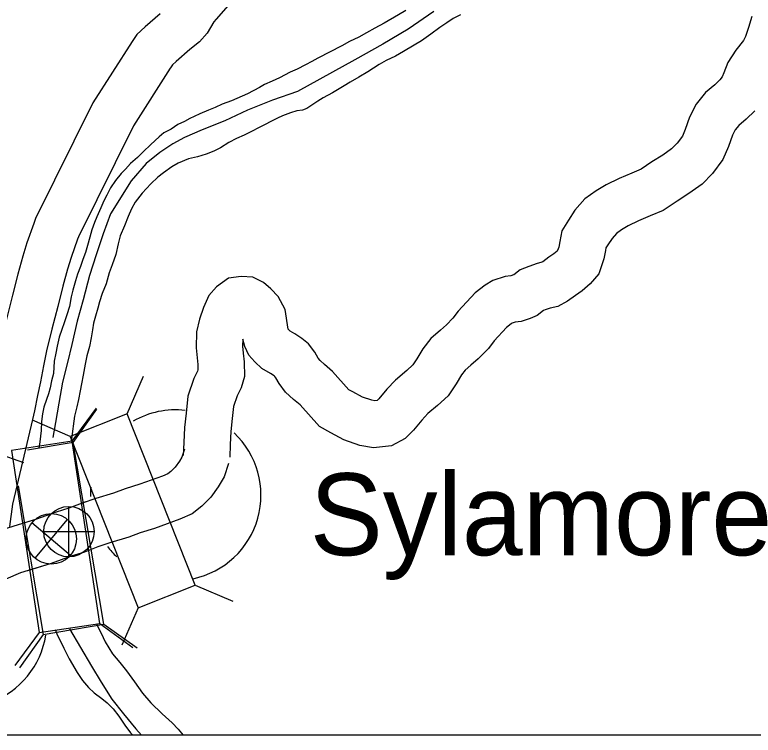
# Model space of a CAD drawing. Extents: x 1377389 to 1380723, y 1168351 to 1170484.
# Drawn here: x 1377861.18 to 1377908.8, y 1169604.28 to 1169650.73 of the extents above; entities that cross this region are included whole.
import ezdxf

# ---------------------------------------------------------------- set-up
doc = ezdxf.new("R2010")
doc.units = 0
doc.layers.add('B_Fill', color=7, linetype='Continuous')
doc.layers.add('B_Text', color=7, linetype='Continuous')

msp = doc.modelspace()

# ---------------------------------------------------------------- linework, layer by layer
at = {"layer": 'B_Fill'}
for p, q in [((1377868.434, 1169625.009), (1377869.481, 1169627.432)), ((1377864.89, 1169623.242), (1377866.456, 1169625.368)), ((1377864.942, 1169623.153), (1377866.471, 1169625.305)), ((1377864.753, 1169623.549), (1377862.329, 1169624.596)), ((1377861.775, 1169621.842), (1377854.923, 1169624.283)), ((1377864.942, 1169623.153), (1377861.997, 1169622.654)), ((1377866.927, 1169611.44), (1377864.942, 1169623.153)), ((1377861.398, 1169620.367), (1377863.023, 1169610.778)), ((1377864.674, 1169615.783), (1377864.674, 1169619.033)), ((1377862.294, 1169617.988), (1377864.783, 1169615.899)), ((1377862.494, 1169615.699), (1377864.583, 1169618.188)), ((1377863.049, 1169617.408), (1377866.299, 1169617.408)), ((1377872.813, 1169613.966), (1377875.236, 1169612.918)), ((1377869.132, 1169612.506), (1377868.085, 1169610.082)), ((1377863.023, 1169610.778), (1377866.927, 1169611.44)), ((1377866.67, 1169611.496), (1377868.795, 1169609.93)), ((1377866.927, 1169611.44), (1377869.079, 1169609.911)), ((1377862.754, 1169610.903), (1377861.188, 1169608.778)), ((1377863.023, 1169610.778), (1377861.494, 1169608.626))]:
    msp.add_line(p, q, dxfattribs=at)
for points in [[(1377874.94, 1169651.321), (1377874.171, 1169650.441), (1377874.024, 1169650.265), (1377873.8, 1169649.909), (1377873.579, 1169649.536), (1377873.097, 1169648.977), (1377872.473, 1169648.484), (1377871.587, 1169647.715), (1377871.346, 1169647.492), (1377871.221, 1169647.303), (1377871.206, 1169647.277)], [(1377886.404, 1169651.005), (1377885.931, 1169650.722), (1377884.995, 1169650.185), (1377884.402, 1169649.868), (1377883.86, 1169649.562), (1377883.377, 1169649.278), (1377882.773, 1169649.001), (1377882.27, 1169648.727), (1377880.72, 1169647.922), (1377880.335, 1169647.721), (1377879.93, 1169647.5), (1377879.397, 1169647.224), (1377878.931, 1169647.031), (1377878.25, 1169646.672), (1377877.775, 1169646.448), (1377877.291, 1169646.234), (1377876.955, 1169646.045), (1377876.195, 1169645.633), (1377875.166, 1169645.174), (1377874.561, 1169644.967), (1377874.096, 1169644.753), (1377873.671, 1169644.571), (1377873.116, 1169644.346), (1377872.75, 1169644.175), (1377872.463, 1169644.047), (1377872.118, 1169643.857), (1377871.693, 1169643.645), (1377871.26, 1169643.353), (1377870.786, 1169643.109), (1377870.492, 1169642.86), (1377870.228, 1169642.622), (1377869.945, 1169642.344), (1377869.486, 1169641.91), (1377869.086, 1169641.538), (1377868.646, 1169641.135), (1377868.325, 1169640.775), (1377868.042, 1169640.487), (1377867.674, 1169640.045), (1377867.366, 1169639.565), (1377867.118, 1169639.097), (1377866.917, 1169638.731), (1377866.729, 1169638.274), (1377866.464, 1169637.705), (1377866.323, 1169637.34), (1377866.156, 1169636.854), (1377866.028, 1169636.389), (1377865.881, 1169635.864), (1377865.753, 1169635.399), (1377865.575, 1169634.942), (1377865.417, 1169634.507), (1377865.229, 1169634.01), (1377865.091, 1169633.575), (1377864.926, 1169632.979), (1377864.828, 1169632.535), (1377864.704, 1169631.919), (1377864.548, 1169631.383), (1377864.371, 1169630.877), (1377864.212, 1169630.441), (1377864.045, 1169629.935), (1377863.91, 1169629.37), (1377863.822, 1169628.916), (1377863.715, 1169628.391), (1377863.686, 1169627.608), (1377863.558, 1169627.123), (1377863.46, 1169626.689), (1377863.35, 1169626.295), (1377863.229, 1169625.93), (1377863.062, 1169625.434), (1377862.973, 1169625.001), (1377862.916, 1169624.518), (1377862.891, 1169623.925), (1377862.8, 1169623.2), (1377862.743, 1169622.785)], [(1377886.404, 1169651.005), (1377885.931, 1169650.722), (1377884.995, 1169650.185), (1377884.402, 1169649.868), (1377883.86, 1169649.562), (1377883.377, 1169649.278), (1377882.773, 1169649.001), (1377882.27, 1169648.727), (1377880.72, 1169647.922), (1377880.335, 1169647.721), (1377879.93, 1169647.5), (1377879.397, 1169647.224), (1377878.931, 1169647.031), (1377878.25, 1169646.672), (1377877.775, 1169646.448), (1377877.291, 1169646.234), (1377876.955, 1169646.045), (1377876.195, 1169645.633), (1377875.166, 1169645.174), (1377874.561, 1169644.967), (1377874.096, 1169644.753), (1377873.671, 1169644.571), (1377873.116, 1169644.346), (1377872.75, 1169644.175), (1377872.463, 1169644.047), (1377872.118, 1169643.857), (1377871.693, 1169643.645), (1377871.26, 1169643.353), (1377870.786, 1169643.109), (1377870.492, 1169642.86), (1377870.228, 1169642.622), (1377869.945, 1169642.344), (1377869.486, 1169641.91), (1377869.086, 1169641.538), (1377868.646, 1169641.135), (1377868.325, 1169640.775), (1377868.042, 1169640.487), (1377867.674, 1169640.045), (1377867.366, 1169639.565), (1377867.118, 1169639.097), (1377866.917, 1169638.731), (1377866.729, 1169638.274), (1377866.464, 1169637.705), (1377866.323, 1169637.34), (1377866.156, 1169636.854), (1377866.028, 1169636.389), (1377865.881, 1169635.864), (1377865.753, 1169635.399), (1377865.575, 1169634.942), (1377865.417, 1169634.507), (1377865.229, 1169634.01), (1377865.091, 1169633.575), (1377864.926, 1169632.979), (1377864.828, 1169632.535), (1377864.704, 1169631.919), (1377864.548, 1169631.383), (1377864.371, 1169630.877), (1377864.212, 1169630.441), (1377864.045, 1169629.935), (1377863.91, 1169629.37), (1377863.822, 1169628.916), (1377863.715, 1169628.391), (1377863.686, 1169627.608), (1377863.558, 1169627.123), (1377863.46, 1169626.689), (1377863.35, 1169626.295), (1377863.229, 1169625.93), (1377863.062, 1169625.434), (1377862.973, 1169625.001), (1377862.916, 1169624.518), (1377862.891, 1169623.925), (1377862.8, 1169623.2), (1377862.779, 1169623.047)], [(1377888.208, 1169650.944), (1377886.556, 1169649.796), (1377884.91, 1169648.828), (1377883.115, 1169647.827), (1377879.405, 1169645.78), (1377877.798, 1169645.225), (1377876.193, 1169644.569), (1377874.73, 1169643.888), (1377873.263, 1169643.316), (1377872.135, 1169642.824), (1377871.375, 1169642.413), (1377870.539, 1169641.858), (1377869.657, 1169641.142), (1377868.695, 1169640.033), (1377867.349, 1169637.9), (1377866.873, 1169636.613), (1377866.438, 1169635.257), (1377866.002, 1169633.931), (1377865.603, 1169632.355), (1377865.209, 1169630.97), (1377864.858, 1169629.466), (1377864.578, 1169628.304), (1377864.271, 1169627.052), (1377864.027, 1169625.681), (1377863.799, 1169624.451), (1377863.631, 1169623.476)], [(1377889.925, 1169650.729), (1377889.451, 1169650.486), (1377889.048, 1169650.214), (1377888.595, 1169649.901), (1377888.006, 1169649.474), (1377887.406, 1169649.056), (1377886.934, 1169648.763), (1377886.244, 1169648.363), (1377885.731, 1169648.058), (1377885.138, 1169647.781), (1377884.684, 1169647.518), (1377883.946, 1169647.057), (1377883.364, 1169646.71), (1377882.802, 1169646.394), (1377882.428, 1169646.143), (1377881.679, 1169645.701), (1377881.067, 1169645.373), (1377880.722, 1169645.154), (1377880.398, 1169644.934), (1377880.014, 1169644.693), (1377879.726, 1169644.585), (1377879.377, 1169644.525), (1377878.96, 1169644.414), (1377878.445, 1169644.219), (1377878.128, 1169644.06), (1377876.894, 1169643.435), (1377876.479, 1169643.223), (1377875.975, 1169642.958), (1377875.48, 1169642.754), (1377874.977, 1169642.49), (1377874.455, 1169642.155), (1377874.02, 1169641.932), (1377873.515, 1169641.738), (1377872.969, 1169641.573), (1377872.391, 1169641.447), (1377871.728, 1169641.158), (1377871.314, 1169640.926), (1377870.774, 1169640.54), (1377870.411, 1169640.26), (1377869.951, 1169639.826), (1377869.407, 1169639.219), (1377868.941, 1169638.645), (1377868.702, 1169638.227), (1377868.485, 1169637.72)], [(1377889.925, 1169650.729), (1377889.451, 1169650.486), (1377889.048, 1169650.214), (1377888.595, 1169649.901), (1377888.006, 1169649.474), (1377887.406, 1169649.056), (1377886.934, 1169648.763), (1377886.244, 1169648.363), (1377885.731, 1169648.058), (1377885.138, 1169647.781), (1377884.684, 1169647.518), (1377883.946, 1169647.057), (1377883.364, 1169646.71), (1377882.802, 1169646.394), (1377882.428, 1169646.143), (1377881.679, 1169645.701), (1377881.067, 1169645.373), (1377880.722, 1169645.154), (1377880.398, 1169644.934), (1377880.014, 1169644.693), (1377879.726, 1169644.585), (1377879.377, 1169644.525), (1377878.96, 1169644.414), (1377878.445, 1169644.219), (1377878.128, 1169644.06), (1377876.894, 1169643.435), (1377876.479, 1169643.223), (1377875.975, 1169642.958), (1377875.48, 1169642.754), (1377874.977, 1169642.49), (1377874.455, 1169642.155), (1377874.02, 1169641.932), (1377873.515, 1169641.738), (1377872.969, 1169641.573), (1377872.391, 1169641.447), (1377871.728, 1169641.158), (1377871.314, 1169640.926), (1377870.774, 1169640.54), (1377870.411, 1169640.26), (1377869.951, 1169639.826), (1377869.407, 1169639.219), (1377868.941, 1169638.645), (1377868.702, 1169638.227), (1377868.485, 1169637.72)], [(1377870.559, 1169650.795), (1377869.585, 1169649.949), (1377869.044, 1169649.449), (1377868.756, 1169649.013)], [(1377908.71, 1169650.617), (1377908.487, 1169649.916), (1377908.306, 1169649.338), (1377908.158, 1169649.06), (1377907.671, 1169648.44), (1377907.165, 1169647.647), (1377906.91, 1169646.98), (1377906.79, 1169646.735), (1377906.636, 1169646.526), (1377906.318, 1169646.22), (1377905.727, 1169645.71), (1377905.11, 1169644.968), (1377904.695, 1169644.138), (1377904.412, 1169643.331), (1377904.228, 1169642.91), (1377903.89, 1169642.456), (1377903.535, 1169642.094), (1377902.967, 1169641.684), (1377902.265, 1169641.24), (1377901.562, 1169640.775), (1377900.968, 1169640.525), (1377900.155, 1169640.169), (1377899.311, 1169639.768), (1377898.662, 1169639.383), (1377897.947, 1169638.868), (1377897.303, 1169638.13), (1377896.882, 1169637.498), (1377896.466, 1169636.802), (1377896.321, 1169636.109), (1377896.258, 1169635.757), (1377896.181, 1169635.531), (1377896.148, 1169635.491), (1377895.944, 1169635.316), (1377895.615, 1169635.093), (1377895.222, 1169634.811), (1377895.111, 1169634.751), (1377894.862, 1169634.691), (1377894.333, 1169634.511), (1377893.773, 1169634.279), (1377893.365, 1169633.97), (1377893.347, 1169633.963), (1377893.169, 1169633.901), (1377892.797, 1169633.861), (1377892.006, 1169633.596), (1377891.505, 1169633.3), (1377890.864, 1169632.805), (1377889.762, 1169631.628), (1377889.425, 1169631.162), (1377889.01, 1169630.74), (1377888.624, 1169630.405), (1377888.002, 1169629.864), (1377887.496, 1169629.186), (1377887.109, 1169628.547), (1377886.848, 1169628.154), (1377886.457, 1169627.806), (1377885.726, 1169627.178), (1377885.175, 1169626.584), (1377884.663, 1169625.972), (1377884.552, 1169625.858), (1377884.402, 1169625.841), (1377884.195, 1169625.876), (1377883.612, 1169626.088), (1377882.978, 1169626.414), (1377882.723, 1169626.556), (1377881.677, 1169627.729), (1377881.151, 1169628.174), (1377880.871, 1169628.433), (1377880.744, 1169628.6), (1377880.529, 1169628.984), (1377880.121, 1169629.506), (1377879.688, 1169629.866), (1377879.248, 1169630.155), (1377878.937, 1169630.337), (1377878.828, 1169630.441), (1377878.821, 1169630.466), (1377878.613, 1169631.737), (1377878.165, 1169632.559), (1377877.695, 1169633.054), (1377877.217, 1169633.474), (1377876.538, 1169633.806), (1377875.775, 1169633.857), (1377874.954, 1169633.75), (1377874.187, 1169633.183), (1377873.699, 1169632.623), (1377873.354, 1169631.851), (1377873.092, 1169631.096), (1377872.907, 1169630.293), (1377872.869, 1169629.266), (1377872.934, 1169628.607), (1377872.98, 1169628.183), (1377872.983, 1169627.834), (1377872.962, 1169627.763), (1377872.734, 1169627.275), (1377872.351, 1169626.134), (1377872.226, 1169625.047), (1377872.124, 1169624.115), (1377872.075, 1169623.155), (1377872.046, 1169622.319)], [(1377868.756, 1169649.013), (1377866.218, 1169645.047), (1377862.523, 1169637.593)], [(1377871.206, 1169647.277), (1377868.833, 1169643.568), (1377865.287, 1169636.414)], [(1377908.901, 1169644.542), (1377908.34, 1169644.002), (1377907.874, 1169643.6), (1377907.638, 1169643.316), (1377907.463, 1169642.966), (1377907.206, 1169642.234), (1377906.842, 1169641.397), (1377906.174, 1169640.499), (1377905.496, 1169639.81), (1377904.649, 1169639.198), (1377903.894, 1169638.721), (1377902.984, 1169638.118), (1377902.152, 1169637.768), (1377901.401, 1169637.439), (1377900.723, 1169637.117), (1377900.307, 1169636.871), (1377899.981, 1169636.636), (1377899.692, 1169636.305), (1377899.42, 1169635.896), (1377899.299, 1169635.694), (1377899.266, 1169635.539), (1377899.172, 1169635.005), (1377898.84, 1169634.035), (1377898.291, 1169633.377), (1377897.77, 1169632.931), (1377897.332, 1169632.632), (1377896.822, 1169632.267), (1377896.202, 1169631.927), (1377895.695, 1169631.806), (1377895.391, 1169631.702), (1377895.277, 1169631.655), (1377894.861, 1169631.34), (1377894.404, 1169631.154), (1377893.827, 1169630.954), (1377893.441, 1169630.913), (1377893.259, 1169630.852), (1377893.189, 1169630.811), (1377892.889, 1169630.578), (1377892.082, 1169629.717), (1377891.724, 1169629.221), (1377891.066, 1169628.551), (1377890.591, 1169628.14), (1377890.214, 1169627.812), (1377889.986, 1169627.507), (1377889.644, 1169626.942), (1377889.134, 1169626.171), (1377888.43, 1169625.546), (1377887.81, 1169625.014), (1377887.426, 1169624.6), (1377886.89, 1169623.959), (1377886.352, 1169623.407), (1377885.471, 1169622.946), (1377884.322, 1169622.81), (1377883.423, 1169622.965), (1377882.409, 1169623.333), (1377881.561, 1169623.769), (1377880.821, 1169624.182), (1377879.578, 1169625.575), (1377879.162, 1169625.927), (1377878.642, 1169626.409), (1377878.229, 1169626.95), (1377878.024, 1169627.317), (1377877.956, 1169627.404), (1377877.898, 1169627.452), (1377877.665, 1169627.606), (1377877.123, 1169627.922), (1377876.671, 1169628.352), (1377876.274, 1169628.786), (1377876.013, 1169629.346), (1377875.891, 1169629.813), (1377875.874, 1169629.358), (1377875.918, 1169628.916), (1377875.978, 1169628.36), (1377875.988, 1169627.405), (1377875.771, 1169626.687), (1377875.524, 1169626.159), (1377875.295, 1169625.478), (1377875.208, 1169624.713), (1377875.116, 1169623.875), (1377875.072, 1169623.026), (1377875.044, 1169622.215)], [(1377862.523, 1169637.593), (1377862.407, 1169637.271), (1377861.963, 1169636.029), (1377861.7, 1169635.175), (1377861.376, 1169634), (1377861.045, 1169632.656), (1377860.664, 1169631.194), (1377860.299, 1169629.729), (1377860.087, 1169628.672), (1377859.901, 1169627.67), (1377859.707, 1169626.818), (1377859.509, 1169625.811), (1377859.391, 1169625.263)], [(1377868.485, 1169637.72), (1377868.25, 1169637.132), (1377867.977, 1169636.482), (1377867.851, 1169635.957), (1377867.708, 1169635.281), (1377867.456, 1169634.612), (1377867.269, 1169634.085), (1377867.077, 1169633.388), (1377866.823, 1169632.769), (1377866.657, 1169632.233), (1377866.548, 1169631.819), (1377866.381, 1169631.303), (1377866.253, 1169630.848), (1377866.185, 1169630.414), (1377866.108, 1169629.901), (1377866.002, 1169629.346), (1377865.838, 1169628.75), (1377865.712, 1169628.215), (1377865.591, 1169627.489), (1377865.485, 1169626.945), (1377865.397, 1169626.491), (1377865.291, 1169625.936), (1377865.193, 1169625.462), (1377865.029, 1169624.846), (1377864.838, 1169623.386), (1377864.808, 1169623.23)], [(1377868.485, 1169637.72), (1377868.25, 1169637.132), (1377867.977, 1169636.482), (1377867.851, 1169635.957), (1377867.708, 1169635.281), (1377867.456, 1169634.612), (1377867.269, 1169634.085), (1377867.077, 1169633.388), (1377866.823, 1169632.769), (1377866.657, 1169632.233), (1377866.548, 1169631.819), (1377866.381, 1169631.303), (1377866.253, 1169630.848), (1377866.185, 1169630.414), (1377866.108, 1169629.901), (1377866.002, 1169629.346), (1377865.838, 1169628.75), (1377865.712, 1169628.215), (1377865.591, 1169627.489), (1377865.485, 1169626.945), (1377865.397, 1169626.491), (1377865.291, 1169625.936), (1377865.193, 1169625.462), (1377865.029, 1169624.846), (1377864.838, 1169623.386), (1377864.835, 1169623.373)], [(1377865.287, 1169636.414), (1377865.23, 1169636.257), (1377864.811, 1169635.082), (1377864.58, 1169634.334), (1377864.279, 1169633.242), (1377863.953, 1169631.919), (1377863.571, 1169630.454), (1377863.227, 1169629.07), (1377863.032, 1169628.102), (1377862.839, 1169627.064), (1377862.642, 1169626.195), (1377862.447, 1169625.207), (1377862.325, 1169624.635)], [(1377862.325, 1169624.635), (1377861.039, 1169619.181), (1377860.853, 1169617.74)], [(1377872.118, 1169622.728), (1377871.952, 1169622.214), (1377871.794, 1169621.959), (1377871.521, 1169621.573), (1377871.239, 1169621.296), (1377871.042, 1169621.137), (1377870.706, 1169620.991), (1377869.247, 1169620.459), (1377868.293, 1169620.177), (1377867.558, 1169619.885), (1377866.419, 1169619.545), (1377865.529, 1169619.253), (1377864.674, 1169618.922), (1377863.86, 1169618.665), (1377862.585, 1169618.21), (1377861.543, 1169617.888)], [(1377874.973, 1169621.806), (1377874.694, 1169620.944), (1377874.295, 1169620.301), (1377873.816, 1169619.623), (1377873.239, 1169619.054), (1377872.612, 1169618.549), (1377871.82, 1169618.204), (1377870.186, 1169617.608), (1377869.273, 1169617.338), (1377868.542, 1169617.048), (1377867.316, 1169616.682), (1377866.539, 1169616.427), (1377865.67, 1169616.09), (1377864.816, 1169615.821), (1377863.532, 1169615.363), (1377862.001, 1169614.889)], [(1377865.754, 1169619.327), (1377865.529, 1169619.253), (1377864.674, 1169618.922), (1377863.86, 1169618.665), (1377862.585, 1169618.21), (1377857.984, 1169616.787)], [(1377866.219, 1169616.303), (1377865.67, 1169616.09), (1377864.816, 1169615.821), (1377863.532, 1169615.363), (1377861.547, 1169614.749), (1377860.599, 1169614.35), (1377860.266, 1169614.276)], [(1377863.778, 1169611.092), (1377863.896, 1169610.82), (1377864.351, 1169609.9), (1377864.689, 1169609.207), (1377865.203, 1169608.318), (1377865.547, 1169607.805), (1377865.929, 1169607.364), (1377866.308, 1169607.023), (1377866.788, 1169606.655), (1377867.146, 1169606.374), (1377867.536, 1169605.993), (1377867.899, 1169605.521), (1377868.284, 1169604.94), (1377868.648, 1169604.448), (1377868.804, 1169604.285)], [(1377864.711, 1169611.151), (1377866.133, 1169608.744), (1377866.761, 1169607.698), (1377867.45, 1169606.613), (1377868.195, 1169605.66), (1377868.992, 1169604.688), (1377869.349, 1169604.285)], [(1377866.432, 1169611.477), (1377866.758, 1169610.858), (1377867.022, 1169610.313), (1377867.483, 1169609.533), (1377867.948, 1169608.974), (1377868.383, 1169608.444), (1377868.912, 1169607.726), (1377869.421, 1169607.007), (1377869.948, 1169606.379), (1377870.678, 1169605.667), (1377871.323, 1169605.092), (1377871.715, 1169604.672), (1377872.048, 1169604.285)], [(1377866.521, 1169611.308), (1377866.758, 1169610.858), (1377867.022, 1169610.313), (1377867.483, 1169609.533), (1377867.948, 1169608.974), (1377868.383, 1169608.444), (1377868.912, 1169607.726), (1377869.421, 1169607.007), (1377869.948, 1169606.379), (1377870.678, 1169605.667), (1377871.323, 1169605.092), (1377871.715, 1169604.672), (1377872.048, 1169604.285)], [(1377863.877, 1169610.865), (1377863.896, 1169610.82), (1377864.351, 1169609.9), (1377864.689, 1169609.207), (1377865.203, 1169608.318), (1377865.547, 1169607.805), (1377865.929, 1169607.364), (1377866.308, 1169607.023), (1377866.788, 1169606.655), (1377867.146, 1169606.374), (1377867.536, 1169605.993), (1377867.899, 1169605.521), (1377868.284, 1169604.94), (1377868.648, 1169604.448), (1377868.804, 1169604.285)]]:
    msp.add_lwpolyline(points, dxfattribs=at)
for points in [[(1377864.753, 1169623.549), (1377869.132, 1169612.506), (1377872.813, 1169613.966), (1377868.434, 1169625.009)], [(1377866.67, 1169611.496), (1377864.89, 1169623.242), (1377860.974, 1169622.649), (1377862.754, 1169610.903)]]:
    msp.add_lwpolyline(points, close=True, dxfattribs=at)
for centre in [(1377864.674, 1169617.408), (1377863.538, 1169616.943)]:
    msp.add_circle(centre, 1.625, dxfattribs=at)
for centre, start, end in [((1377871.559, 1169619.759), 83.6598, 119.859), ((1377871.559, 1169619.759), 281.8421, 46.8476), ((1377871.559, 1169619.759), 174.5597, 180.9094), ((1377871.559, 1169619.759), 216.8699, 226.2454), ((1377857.75, 1169611.581), 290.1576, 351.2538)]:
    msp.add_arc(centre, 5.5, start, end, dxfattribs=at)
at = {"layer": 'B_Text'}
msp.add_lwpolyline([(1377549.76, 1170388.771), (1378279.156, 1170388.771), (1378279.156, 1169604.285), (1377549.76, 1169604.285)], close=True, dxfattribs=at)

# ---------------------------------------------------------------- texts
at = {"layer": 'B_Fill'}
msp.add_text('Sylamore', height=5.28, dxfattribs=at).set_placement((1377880.202, 1169615.888))

doc.saveas('drawing.dxf')
